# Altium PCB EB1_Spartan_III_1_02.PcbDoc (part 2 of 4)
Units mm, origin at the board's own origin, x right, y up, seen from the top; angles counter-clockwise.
Board outline 165.1 x 115.01 mm, 6 copper layers (Top Layer, MidLayer1, VCC Plane, GND Plane, MidLayer2, Bottom Layer); 356 components, 386 nets, 1788 pads, 779 vias.
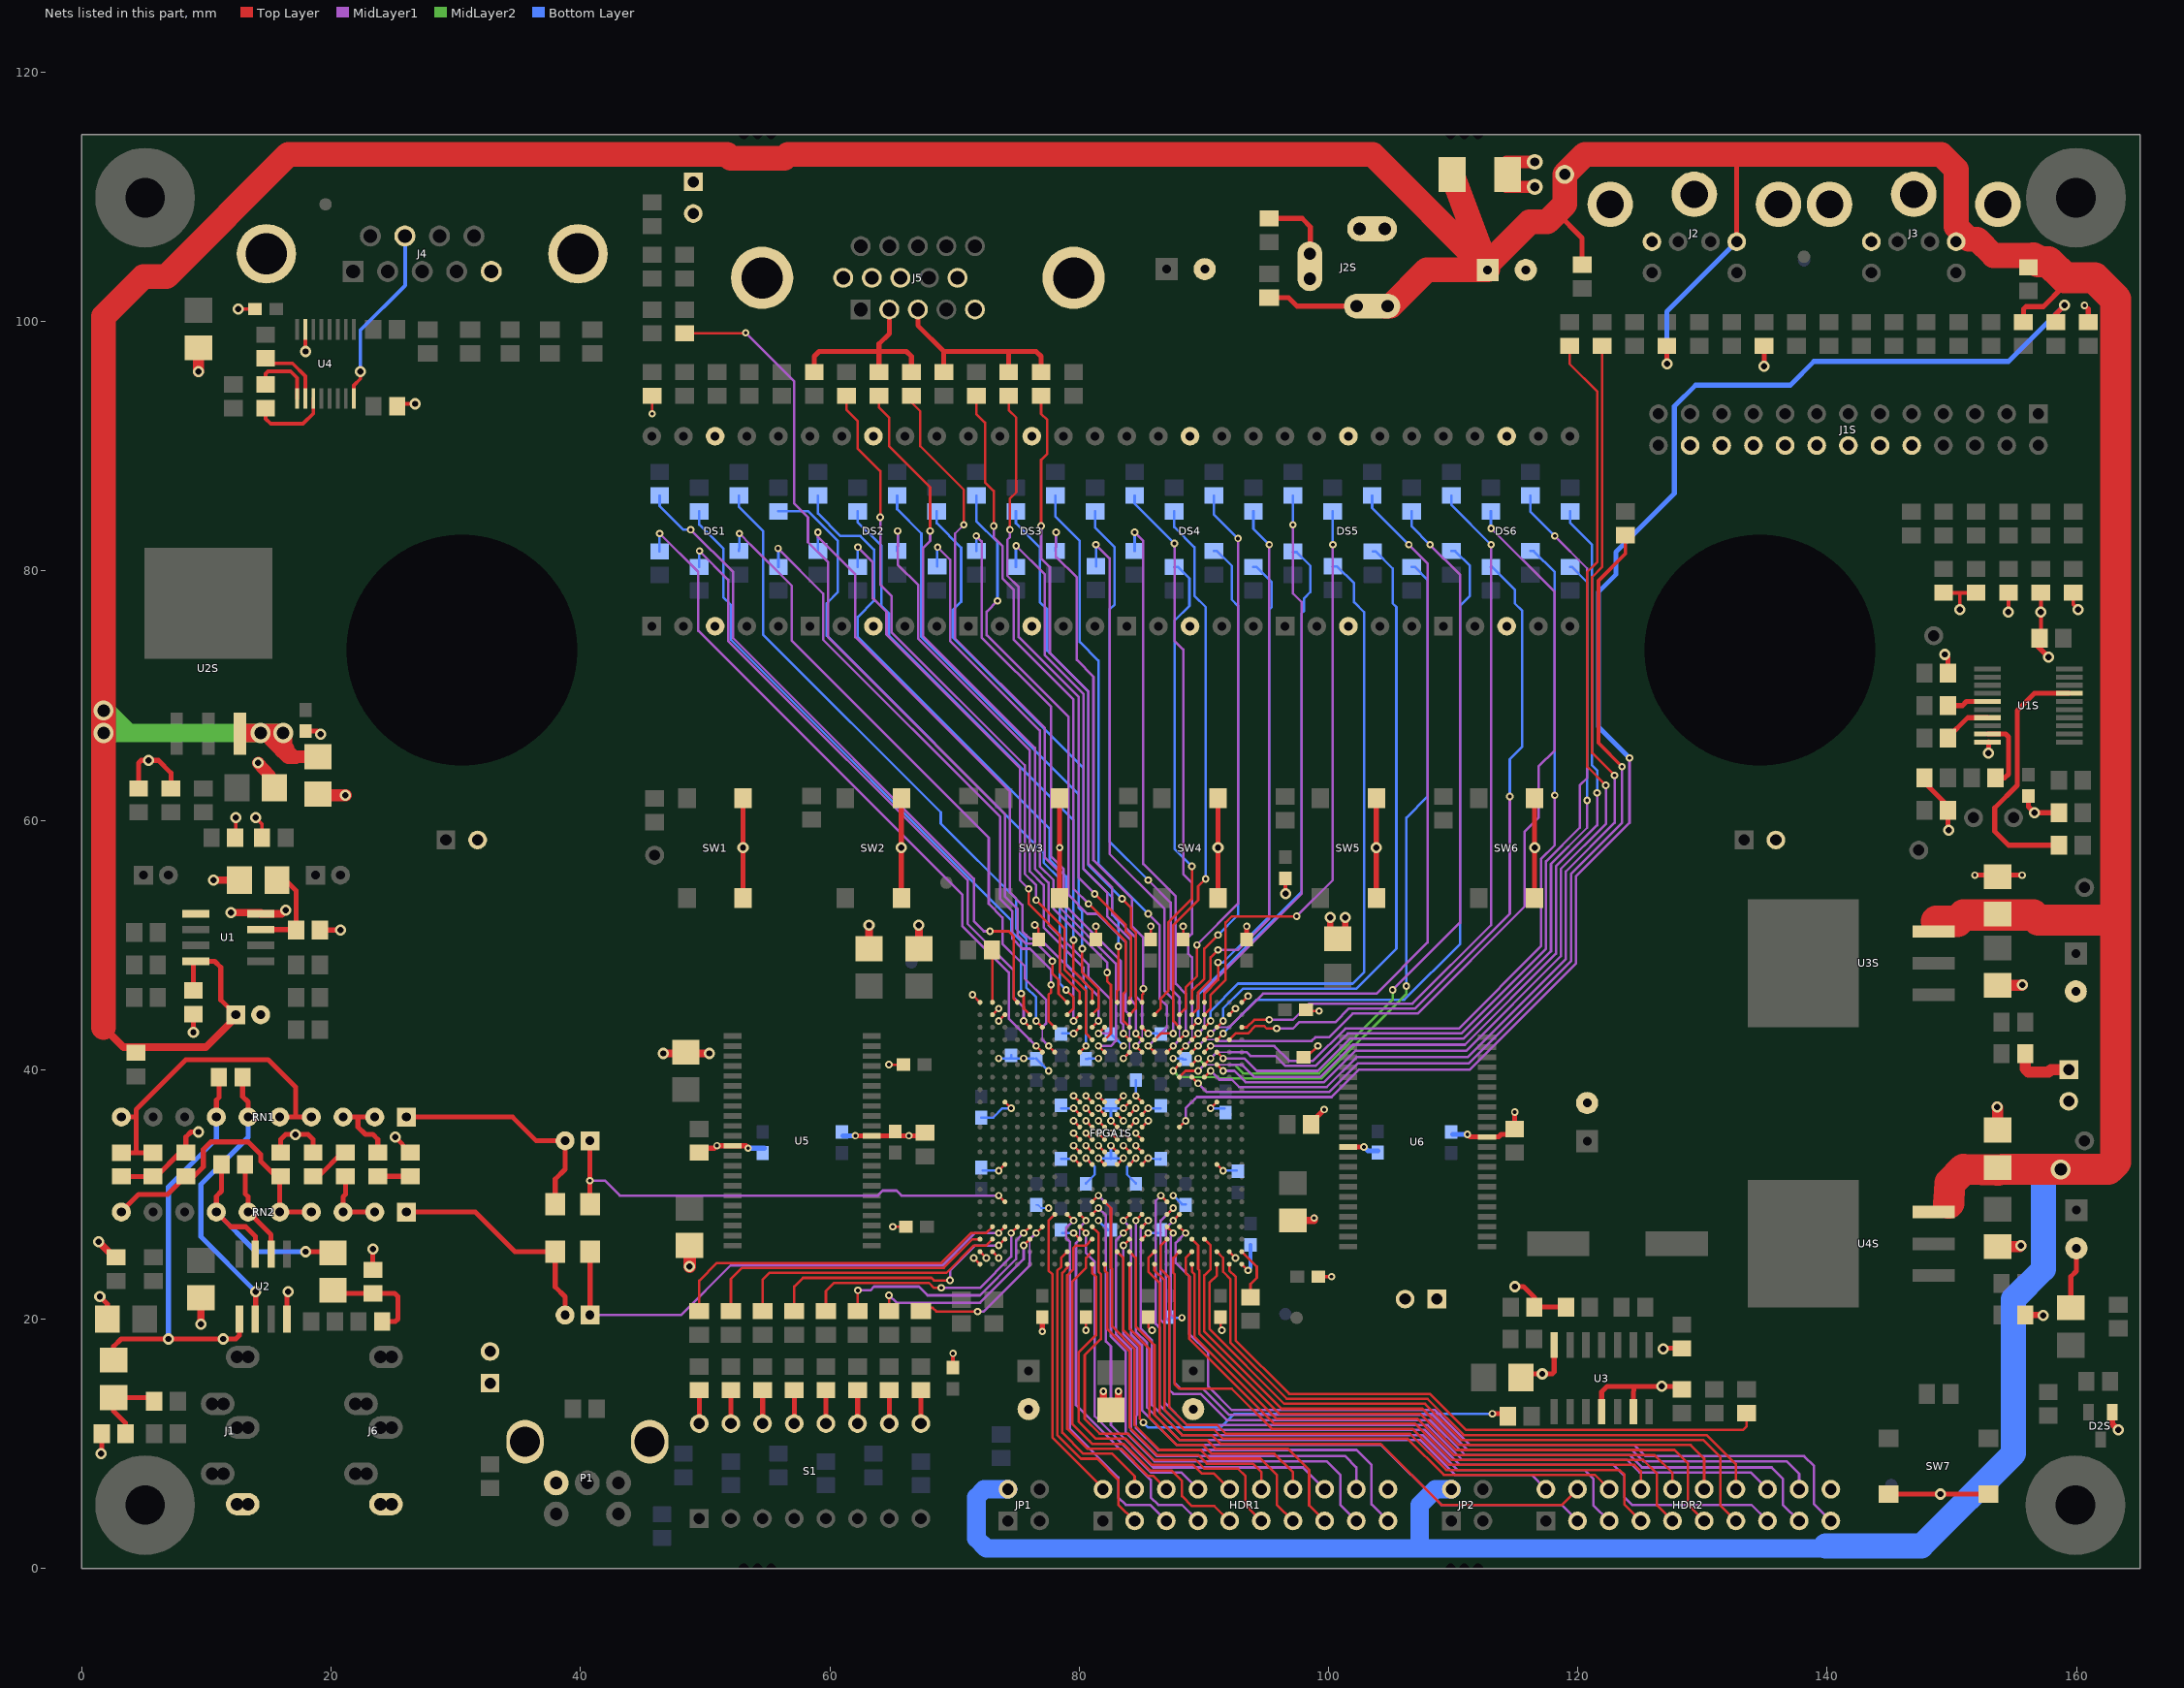
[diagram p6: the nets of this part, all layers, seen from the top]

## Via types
v1: diameter 0.6, hole 0.3, Top Layer to Bottom Layer, tented both sides, 427 vias
v2: diameter 1.6, hole 1, Top Layer to Bottom Layer, 224 vias
v3: diameter 0.9, hole 0.5, Top Layer to Bottom Layer, tented both sides, 126 vias
v4: diameter 1.27, hole 0.711, Top Layer to Bottom Layer, tented both sides, 2 vias

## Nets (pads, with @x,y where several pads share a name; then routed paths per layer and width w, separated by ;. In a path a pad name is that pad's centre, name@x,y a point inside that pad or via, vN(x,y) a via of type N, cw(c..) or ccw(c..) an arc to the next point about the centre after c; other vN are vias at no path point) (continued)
+5V: C37.1 C39.2 C70S.1 C73S.1 C75S.1 C77S.1 D1S.2 J2.5 J2S.1 J2S.1A J2S.1B J3.5 JP1.2 JP2.2 LED1.1 R6.2 R84.1 R85.1 R86.1 R87.1 TP6S.1 U1.8 U2S.3 U3S.3 U4S.3 | length 580.3
  Top Layer w0.4: C39.2@8.95,46.35 U1.8@8.95,48.6 ; U1.8@9.15,48.695 10.655,48.695 11.15,48.2 11.15,45.6 C37.1@12.35,44.4 ; LED1.1@95.25,101.92 96.8,101.92 97.485,101.235 J2S.1A@102.255,101.235 ; J2S.1@102.2,101.3 102.255,101.3 J2S.1@103.45,101.3 ; J2S.1@103.505,101.235 J2S.1@104.55,101.235 ; 118.25,108.8 118.3,108.75 120.35,106.7 R86.1@120.35,104.55 ; 122.55,113.4 122.555,113.595 125.65,113.4 ; v3(127.15,96.6) R87.1@127.15,98.05 ; 132.65,113.3 132.75,113.2 J2.5@132.75,106.4 ; R84.1@155.75,99.95 155.75,101 155.95,101.2 157.35,101.2 158.95,102.8
  Top Layer w0.6: 1.75,43.8 1.75,43.4 3.35,41.8 R6.2@4.35,41.8 ; R6.2@4.35,41.35 R6.2@4.35,41.8 ; C37.1@12.35,44.4 12.35,44.2 9.95,41.8 R6.2@4.35,41.8
  Top Layer w1: v2@14.75,66.8 15.35,66.2 16.55,65 17.15,65 ; v2@15.7,66.95 16.139,66.901 v2@16.15,66.9 ; 16.15,65.4 16.15,65.5 ; 16.15,65.7 16.15,65.5 ; v2(16.15,67) v2@16.15,66.9 ; 16.55,65.7 16.55,65.8 ; 16.95,65.2 16.15,66 v2@16.15,66.9 ; C73S.1@18.95,65.1 16.55,65.1 16.2,65.45 16.15,65.5
  Top Layer w1.5: U2S.3@12.95,67 v2(14.35,67) v2(16.15,67) 16.15,66.9 16.15,66 16.15,65.7
  Top Layer w2: 1.75,43.4 v2(1.75,67) v2(1.75,68.8) 1.75,100.4 4.95,103.6 6.784,103.6 16.55,113.4 51.75,113.4 52.05,113.1 56.35,113.1 56.65,113.4 103.55,113.4 C70S.1@112.776,104.14 ; J2S.1@104.55,101.235 J2S.1B@104.755,101.235 104.985,101.235 107.89,104.14 C70S.1@112.776,104.14 ; D1S.2@109.928,111.8 C70S.1@112.776,104.14 ; C70S.1@112.776,104.626 116.15,108 117.55,108 118.3,108.75 118.95,109.4 TP6S.1@118.95,111.8 120.55,113.4 122.55,113.4 125.65,113.4 149.15,113.4 150.35,112.2 150.35,107.6 150.95,107 151.35,106.6 152.05,106.6 153.35,105.3 156.15,105.3 156.65,105.3
  Top Layer w2.5: 148.75,51.9 150.45,51.9 150.95,52.4 153.67,52.4 156.55,52.4 156.95,52 163.15,52 ; 149.75,29.3 149.782,29.617 149.85,30.9 150.95,32 153.666,31.953 153.696,31.952 154.07,32 v2(158.75,32) 162.55,32 163.15,32.6 163.15,52 ; 156.551,105.096 156.775,104.975 156.95,104.8 157.75,104.8 159.05,103.5 161.45,103.5 163.15,101.8 163.15,52
  MidLayer2 w1.5: v2(16.15,67) v2(14.35,67) 3.75,67 ; 3.75,67 2.75,68 1.95,68.8 v2(1.75,68.8) v2(1.75,67) 3.75,67
  Bottom Layer w0.4: v3(127.15,96.6) 127.15,100.8 J2.5@132.75,106.4
  Bottom Layer w1.5: JP1.2@74.295,6.35 72.39,6.35 71.755,5.715 71.755,2.395 72.55,1.6 139.69,1.6 139.89,1.8 ; 107.315,1.905 107.315,5.08 108.585,6.35 JP2.2@109.855,6.35
  Bottom Layer w2: 139.89,1.8 147.55,1.8 154.95,9.2 154.95,21.6 157.35,24 157.35,32 ; 156.95,32 157.35,32 ; v2(158.75,32) 157.35,32
AUDIOL: C7.1 C41.1 FPGA1S.W3 | length 41.3
  Top Layer w0.2: v1(73.55,26.9) FPGA1S.W3@74.05,27.4
  Top Layer w0.4: C41.1@40.767,20.32 40.77,20.323 C7.1@40.77,25.4
  MidLayer1 w0.2: C41.1@40.767,20.32 48.07,20.32 52.05,24.3 69.05,24.3 71.65,26.9 v1(73.55,26.9)
AUDIOR: C6.1 C40.1 FPGA1S.U3 | length 39.4
  Top Layer w0.2: v1(73.55,29.9) FPGA1S.U3@74.05,29.4
  Top Layer w0.4: C40.1@40.767,34.29 40.767,31.1 40.767,29.213 C6.1@40.77,29.21
  MidLayer1 w0.2: v1(40.75,31.1) 41.95,31.1 43.15,29.9 63.85,29.9 64.25,30.3 65.35,30.3 65.75,29.9 v1(73.55,29.9)
BLUE0: FPGA1S.C13 R106.1 | length 55.9
  Top Layer w0.2: R106.1@71.75,94.05 71.75,92.6 72.45,91.9 72.45,87.1 73.15,86.4 v1(73.15,83.6) ; v1(80.75,53.3) 83.75,50.3 83.75,46.3 83.55,46.1 83.55,43.9 FPGA1S.C13@84.05,43.4
  MidLayer1 w0.2: v1(73.15,83.6) 73.15,82.7 73.85,82 73.85,79.4 74.75,78.5 74.75,74.5 79.55,69.7 79.55,54.5 v1(80.75,53.3)
BLUE1: FPGA1S.A13 R108.1 | length 53.3
  Top Layer w0.2: R108.1@74.35,94.05 74.35,92.9 74.95,92.3 74.95,86.3 74.45,85.8 v1(74.45,83.3) ; v1(81.25,54.1) 83.75,51.6 83.75,51.1 84.15,50.7 84.15,45.9 84.05,45.8 FPGA1S.A13@84.05,45.4
  MidLayer1 w0.2: v1(74.45,83.3) 74.45,82.7 74.25,82.5 74.25,79.6 75.15,78.7 75.15,74.7 79.95,69.9 79.95,55.4 v1(81.25,54.1)
BLUE2: FPGA1S.E14 R111.1 | length 56.8
  Top Layer w0.2: v1(76.95,83.6) 76.95,88.9 77.45,89.4 77.45,92.1 76.95,92.6 R111.1@76.95,94.05 ; v1(84.55,41.9) FPGA1S.E14@85.05,41.4
  MidLayer1 w0.127: 85.05,42.4 85.05,43.4
  MidLayer1 w0.2: v1(76.95,83.6) 76.95,81 77.65,80.3 77.65,73.4 80.75,70.3 80.75,56.5 82.65,54.6 82.65,52.5 84.55,50.6 84.55,45.9 85.05,45.4 85.05,43.4 ; v1(84.55,41.9) 85.05,42.4
BLUE#: J5.3 R107.2 R108.2 R111.2 | length 16.7
  Top Layer w0.4: J5.3@67.064,100.965 67.064,99.686 69.15,97.6 ; R107.2@69.15,95.95 69.15,97.6 ; R108.2@74.35,95.95 74.35,97.6 ; R111.2@76.95,96 76.95,97.2 76.55,97.6 74.35,97.6 ; 69.15,97.6 74.35,97.6
CTS: J4.7 U4.8 | length 14.8
  Top Layer w0.3: U4.8@21.825,93.825 21.825,94.875 22.35,95.4 v3(22.35,96)
  Bottom Layer w0.3: v3(22.35,96) 22.35,99.3 25.95,102.9 25.95,106.825 J4.7@25.92,106.855
DIG0_SEG0: FPGA1S.C6 R25.2 | length 52.7
  Top Layer w0.2: v1(76.55,43.9) FPGA1S.C6@77.05,43.4
  Bottom Layer w0.2: R25.2@52.705,86.045 52.705,85.145 54.65,83.2 54.65,74.9 68.906,60.644 68.906,59.744 74.95,53.7 74.95,51.3 75.75,50.5 75.75,46.6 76.55,45.8 v1(76.55,43.9)
DIG0_SEG1: FPGA1S.B8 R29.2 | length 52.5
  Top Layer w0.2: v1(78.95,46.4) 79.55,45.8 79.55,44.9 FPGA1S.B8@79.05,44.4
  Bottom Layer w0.2: R29.2@55.88,84.775 58.275,84.775 60.65,82.4 60.65,78.3 59.75,77.4 59.75,74.8 77.15,57.4 77.15,56.6 78.45,55.3 78.45,46.9 v1(78.95,46.4)
DIG0_SEG2: FPGA1S.E7 R33.2 | length 53.8
  Top Layer w0.2: v1(77.55,41.9) FPGA1S.E7@78.05,41.4
  MidLayer1 w0.127: 77.05,42.4 77.05,43.4
  MidLayer1 w0.2: v1(52.75,83) 53.643,82.093 ; 53.65,82.1 56.95,78.8 56.95,74.4 72.75,58.6 72.75,53.3 73.85,52.2 73.85,50.1 75.65,48.3 75.65,47.3 77.35,45.6 77.35,43.7 77.05,43.4 ; 77.05,42.4 v1(77.55,41.9)
  Bottom Layer w0.2: R33.2@52.705,81.595 52.705,81.755 52.75,81.8 v1(52.75,83)
DIG0_SEG3: FPGA1S.C5 R37.2 | length 50.5
  Top Layer w0.2: v1(75.55,43.9) FPGA1S.C5@76.05,43.4
  MidLayer1 w0.2: v1(49.55,81.6) 51.85,79.3 51.85,74.4 71.05,55.2 71.05,51.7 74.75,48 74.75,45.8 75.55,45 v1(75.55,43.9)
  Bottom Layer w0.2: R37.2@49.53,80.325 49.53,81.58 v1(49.55,81.6)
DIG0_SEG4: FPGA1S.E6 R41.2 | length 55.7
  Top Layer w0.2: v1(76.55,41.9) FPGA1S.E6@77.05,41.4
  MidLayer1 w0.2: v1(46.35,83) 49.45,79.9 49.45,75.2 70.65,54 70.65,51.5 74.35,47.8 74.35,44.1 v1(76.55,41.9)
  Bottom Layer w0.2: R41.2@46.35,81.57 v1(46.35,83)
DIG0_SEG5: FPGA1S.B5 R45.2 | length 51.4
  Top Layer w0.2: v1(75.35,46.1) 75.55,45.9 75.55,44.9 FPGA1S.B5@76.05,44.4
  Bottom Layer w0.2: R45.2@49.53,84.775 49.53,83.72 51.45,81.8 51.45,77.9 52.05,77.3 52.05,74.5 74.55,52 74.55,51.1 75.35,50.3 v1(75.35,46.1)
DIG0_SEG6: FPGA1S.A4 R49.2 | length 54.1
  Top Layer w0.2: v1(72.85,51.1) 74.35,51.1 74.75,50.7 74.75,45.7 FPGA1S.A4@75.05,45.4
  MidLayer1 w0.2: v1(48.85,83.3) 52.25,79.9 52.25,74.6 71.55,55.3 71.55,51.9 72.35,51.1 v1(72.85,51.1)
  Bottom Layer w0.2: R49.2@46.355,86.045 46.355,85.195 48.25,83.3 v1(48.85,83.3)
DIG0_SEG7: FPGA1S.C7 R53.2 | length 49.6
  Top Layer w0.2: v1(77.75,46.8) 77.75,46.2 77.55,46 77.55,43.9 FPGA1S.C7@78.05,43.4
  MidLayer1 w0.2: v1(55.85,81.8) 59.475,78.175 59.475,74.475 73.65,60.3 73.65,53.7 74.65,52.7 74.65,50.5 75.45,49.7 76.05,49.7 77.75,48 v1(77.75,46.8)
  Bottom Layer w0.2: v1(55.85,81.8) 55.88,81.77 R53.2@55.88,80.325
DIG1_SEG0: FPGA1S.B10 R26.2 | length 48.5
  Top Layer w0.2: v1(80.25,49.7) 80.25,47.8 81.55,46.5 81.55,44.9 FPGA1S.B10@81.05,44.4
  Bottom Layer w0.2: R26.2@65.405,86.045 65.405,84.945 67.35,83 67.35,74.7 79.95,62.1 79.95,53 80.25,52.7 v1(80.25,49.7)
DIG1_SEG1: FPGA1S.A12 R30.2 | length 46
  Top Layer w0.2: FPGA1S.A12@83.05,45.4 83.05,46.3 83.15,46.4 v1(83.15,49.9)
  Bottom Layer w0.2: R30.2@68.58,84.775 68.58,83.82 70.536,81.864 70.536,77.521 69.85,76.835 69.85,74.7 80.35,64.2 80.35,56.1 82.65,53.8 82.65,52.4 83.15,51.9 v1(83.15,49.9)
DIG1_SEG2: FPGA1S.C10 R34.2 | length 48.3
  Top Layer w0.2: FPGA1S.C10@81.05,43.4 v1(81.55,43.9)
  MidLayer1 w0.2: v1(65.45,83.2) 65.45,80.5 67.101,78.849 67.101,74.549 76.05,65.6 76.05,55.9 77.15,54.8 77.15,51.4 80.35,48.2 80.35,47.1 81.55,45.9 v1(81.55,43.9)
  Bottom Layer w0.2: R34.2@65.405,81.595 65.405,81.955 65.45,82 v1(65.45,83.2)
DIG1_SEG3: FPGA1S.A9 R38.2 | length 45.5
  Top Layer w0.2: v1(75.95,54.5) 75.95,53.3 78.45,50.8 78.45,47.8 80.05,46.2 FPGA1S.A9@80.05,45.4
  MidLayer1 w0.2: v1(62.25,81.9) 63.45,80.7 63.45,77.8 64.55,76.7 64.55,74.9 75.25,64.2 75.25,55.2 v1(75.95,54.5)
  Bottom Layer w0.2: R38.2@62.23,80.325 62.23,80.48 62.25,80.5 v1(62.25,81.9)
DIG1_SEG4: FPGA1S.B9 R42.2 | length 50.4
  Top Layer w0.2: v1(79.55,43.9) FPGA1S.B9@80.05,44.4
  MidLayer1 w0.2: v1(59.05,83.1) 59.05,82.7 62.05,79.7 62.05,74.7 74.45,62.3 74.45,54.2 75.45,53.2 75.45,51.1 75.761,50.789 76.05,50.5 76.85,50.5 79.55,47.8 v1(79.55,43.9)
  Bottom Layer w0.2: v1(59.05,83.1) 59.055,83.095 R42.2@59.055,81.595
DIG1_SEG5: FPGA1S.A10 R46.2 | length 47.2
  Top Layer w0.2: v1(79.55,50.4) 79.55,47.9 81.05,46.4 FPGA1S.A10@81.05,45.4
  Bottom Layer w0.2: R46.2@62.23,84.775 62.23,83.92 64.15,82 64.15,77.2 64.75,76.6 64.75,74.8 79.55,60 v1(79.55,50.4)
DIG1_SEG6: FPGA1S.E9 R50.2 | length 55.8
  Top Layer w0.2: FPGA1S.E9@80.05,41.4 v1(80.55,41.9)
  Bottom Layer w0.2: R50.2@59.055,86.045 59.055,84.595 60.85,82.8 62.45,82.8 63.55,81.7 63.55,77.6 62.25,76.3 62.25,74.7 77.65,59.3 77.65,56.8 78.95,55.5 78.95,48.5 80.55,46.9 v1(80.55,41.9)
DIG1_SEG7: FPGA1S.D11 R54.2 | length 47
  Top Layer w0.2: FPGA1S.D11@82.05,42.4 82.55,42.9 82.55,46.8 82.25,47.1 v1(82.25,47.8)
  MidLayer1 w0.2: v1(68.65,81.9) 69.65,80.9 69.65,74.4 76.85,67.2 76.85,56.3 77.95,55.2 77.95,52.9 82.25,48.6 v1(82.25,47.8)
  Bottom Layer w0.2: R54.2@68.623,80.347 68.623,81.873 v1(68.65,81.9)
DIG2_SEG0: FPGA1S.E15 R27.2 | length 49.2
  Top Layer w0.2: v1(85.55,41.9) FPGA1S.E15@86.05,41.4
  MidLayer1 w0.127: 87.05,43.4 87.05,44.4
  MidLayer1 w0.2: v1(85.55,41.9) 87.05,43.4 ; v1(85.55,52.5) 86.45,51.6 86.45,45.7 87.05,45.1 87.05,44.4
  Bottom Layer w0.2: R27.2@78.105,86.045 78.105,84.345 80.05,82.4 80.05,74.3 81.55,72.8 81.55,56.5 v1(85.55,52.5)
DIG2_SEG1: FPGA1S.E16 R31.2 | length 46.9
  Top Layer w0.2: FPGA1S.E16@87.05,41.4 v1(87.55,41.9)
  MidLayer1 w0.127: 88.05,42.4 88.05,43.4
  MidLayer1 w0.2: v1(85.55,55.2) 87.35,53.4 87.35,46.5 88.05,45.8 88.05,43.4 ; v1(87.55,41.9) 88.05,42.4
  Bottom Layer w0.2: R31.2@81.28,84.775 81.28,83.47 82.85,81.9 82.85,77.3 82.45,76.9 82.45,58.3 v1(85.55,55.2)
DIG2_SEG2: FPGA1S.A14 R35.2 | length 42.2
  Top Layer w0.2: FPGA1S.A14@85.05,45.4 85.05,46 85.15,46.1 v1(85.15,46.5)
  MidLayer1 w0.2: v1(78.15,83.1) 78.15,81.1 79.814,79.466 79.814,72.866 81.15,71.5 81.15,56.8 84.25,53.7 84.25,51.5 85.15,50.6 v1(85.15,46.5)
  Bottom Layer w0.2: R35.2@78.105,81.595 78.105,81.855 78.15,81.9 v1(78.15,83.1)
DIG2_SEG3: FPGA1S.D14 R39.2 | length 45.5
  Top Layer w0.2: v1(84.55,42.9) FPGA1S.D14@85.05,42.4
  MidLayer1 w0.2: v1(74.95,82) 77.25,79.7 77.25,73.234 80.35,70.134 80.35,56.1 82.25,54.2 82.25,52.3 84.15,50.4 84.15,45.6 84.55,45.2 v1(84.55,42.9)
  Bottom Layer w0.2: R39.2@74.93,80.325 74.93,81.98 v1(74.95,82)
DIG2_SEG4: FPGA1S.D13 R43.2 | length 46.7
  Top Layer w0.2: v1(83.55,42.9) FPGA1S.D13@84.05,42.4
  MidLayer1 w0.2: v1(71.75,82.8) 72.187,82.363 72.187,74.651 77.75,69.1 77.75,57.1 78.75,56.1 78.75,53.3 83.35,48.7 83.35,43.8 83.55,43.6 v1(83.55,42.9)
  Bottom Layer w0.2: v1(71.75,82.8) 71.755,82.795 R43.2@71.755,81.595
DIG2_SEG5: FPGA1S.B13 R47.2 | length 44.6
  Top Layer w0.2: v1(83.45,53.7) 84.15,53 84.15,51.4 84.55,51 84.55,44.9 FPGA1S.B13@84.05,44.4
  Bottom Layer w0.2: R47.2@74.93,84.775 74.93,83.82 76.85,81.9 76.85,77.5 77.45,76.9 77.45,73.6 80.75,70.3 80.75,56.4 v1(83.45,53.7)
DIG2_SEG6: FPGA1S.E13 R51.2 | length 52.3
  Top Layer w0.2: v1(83.55,40.9) FPGA1S.E13@84.05,41.4
  MidLayer1 w0.127: 84.05,41.4 84.05,43.4
  MidLayer1 w0.2: v1(73.45,77.6) 72.593,76.733 72.593,74.854 79.15,68.3 79.15,54 80.65,52.5 81.45,52.5 83.75,50.2 83.75,44.7 84.05,44.4 84.05,43.4 ; v1(83.55,40.9) 84.05,41.4
  Bottom Layer w0.2: R51.2@71.755,86.045 71.755,83.995 73.45,82.3 v1(73.45,77.6)
DIG2_SEG7: FPGA1S.D15 R55.2 | length 45.2
  Top Layer w0.2: FPGA1S.D15@86.05,42.4 86.55,42.9 v1(87.55,42.9)
  MidLayer1 w0.2: v1(81.35,82.1) 82.45,81 82.45,57.3 86.85,52.9 86.85,46.3 87.55,45.6 v1(87.55,42.9)
  Bottom Layer w0.2: R55.2@81.35,80.37 v1(81.35,82.1)
DIG3_SEG0: FPGA1S.B17 R28.2 | length 44.4
  Top Layer w0.2: FPGA1S.B17@88.05,44.4 88.55,44.9 88.55,46.6 89.45,47.5 v1(89.45,50)
  MidLayer1 w0.2: v1(89.45,50) 92.75,53.3 v1(92.75,82.6)
  Bottom Layer w0.2: R28.2@90.805,86.045 90.805,84.545 v1(92.75,82.6)
DIG3_SEG1: FPGA1S.B18 R32.2 | length 44.4
  Top Layer w0.2: FPGA1S.B18@89.05,44.4 89.55,44.9 89.55,46.2 90.55,47.2 90.55,49 v1(91.15,49.6)
  MidLayer1 w0.2: v1(91.15,49.6) 92.75,49.6 95.25,52.1 v1(95.25,82.1)
  Bottom Layer w0.2: R32.2@93.98,84.775 93.98,83.37 v1(95.25,82.1)
DIG3_SEG2: FPGA1S.A18 R36.2 | length 38.7
  Top Layer w0.2: FPGA1S.A18@89.05,45.4 89.05,46.3 90.05,47.3 90.05,49.7 v1(91.15,50.8)
  Bottom Layer w0.2: R36.2@90.805,81.595 91.055,81.595 92.25,80.4 92.25,77.7 92.75,77.2 92.75,52.4 v1(91.15,50.8)
DIG3_SEG3: FPGA1S.B15 R40.2 | length 38.9
  Top Layer w0.2: FPGA1S.B15@86.05,44.4 86.55,44.9 86.55,45.7 87.15,46.3 87.15,51.8 89.05,53.7 v1(89.05,56.3)
  Bottom Layer w0.2: R40.2@87.63,80.325 87.925,80.325 88.85,79.4 88.85,77.2 87.65,76 87.65,57.7 v1(89.05,56.3)
DIG3_SEG4: FPGA1S.D17 R44.2 | length 44.1
  Top Layer w0.2: FPGA1S.D17@88.05,42.4 v1(88.55,42.9)
  MidLayer1 w0.2: v1(84.45,83.1) 85.15,82.4 85.15,56.5 87.75,53.9 87.75,46.9 88.55,46.1 v1(88.55,42.9)
  Bottom Layer w0.2: v1(84.45,83.1) 84.455,83.095 R44.2@84.455,81.595
DIG3_SEG5: FPGA1S.C17 R48.2 | length 43.7
  Top Layer w0.2: FPGA1S.C17@88.05,43.4 87.55,43.9 87.55,51.6 89.55,53.6 89.55,54.7 v1(90.15,55.3)
  Bottom Layer w0.2: R48.2@87.63,84.775 87.63,83.52 89.25,81.9 89.25,78 90.15,77.1 v1(90.15,55.3)
DIG3_SEG6: FPGA1S.E17 R52.2 | length 47.2
  Top Layer w0.2: FPGA1S.E17@88.05,41.4 v1(88.55,41.9)
  MidLayer1 w0.127: 89.05,42.4 89.05,44.4
  MidLayer1 w0.2: v1(87.65,82.2) 87.65,74.4 88.35,73.7 88.35,55.7 89.05,55 89.05,50.9 88.75,50.6 88.75,49.3 89.05,49 89.05,44.4 ; v1(88.55,41.9) 89.05,42.4
  Bottom Layer w0.2: R52.2@84.455,86.045 84.455,85.395 v1(87.65,82.2)
DIG3_SEG7: FPGA1S.A19 R56.2 | length 38.1
  Top Layer w0.2: FPGA1S.A19@90.05,45.4 90.05,46.1 91.15,47.2 v1(91.15,48.6)
  Bottom Layer w0.2: v1(91.15,48.6) 91.55,48.6 95.25,52.3 95.25,76.9 95.45,77.1 95.45,79.1 94.225,80.325 R56.2@93.98,80.325
DIG4_SEG0: FPGA1S.D19 R57.2 | length 58.8
  Top Layer w0.2: FPGA1S.D19@90.05,42.4 v1(90.55,42.9)
  MidLayer1 w0.127: 91.05,43.4 92.05,43.4
  MidLayer1 w0.2: v1(90.55,42.9) 91.05,43.4 ; 92.05,43.4 94.75,46.1 103.85,46.1 107.95,50.2 107.95,80.6 v1(106.45,82.1)
  Bottom Layer w0.2: R57.2@103.505,86.045 103.505,85.045 v1(106.45,82.1)
DIG4_SEG1: FPGA1S.F18 R59.2 | length 62.3
  Top Layer w0.2: FPGA1S.F18@89.05,40.4 v1(89.55,40.9)
  MidLayer1 w0.2: v1(105.15,46.4) 110.55,51.8 110.55,79.7 v1(108.15,82.1)
  MidLayer2 w0.127: 90.023,40.427 90.05,40.4 92.05,40.4
  MidLayer2 w0.2: v1(89.55,40.9) 90.05,40.4 ; 92.05,40.4 92.45,40.4 93.15,39.7 99.25,39.7 105.15,45.6 v1(105.15,46.4)
  Bottom Layer w0.2: R59.2@106.68,84.775 106.68,83.57 v1(108.15,82.1)
DIG4_SEG2: FPGA1S.C20 R61.2 | length 50.4
  Top Layer w0.2: FPGA1S.C20@91.05,43.4 v1(91.55,43.9)
  Bottom Layer w0.2: v1(91.55,43.9) 91.55,44.9 93.15,46.5 102.25,46.5 105.45,49.7 105.45,77.1 105.15,77.4 105.15,80.2 103.78,81.57 R61.2@103.55,81.57
DIG4_SEG3: FPGA1S.C19 R63.2 | length 48.9
  Top Layer w0.2: FPGA1S.C19@90.05,43.4 v1(90.55,43.9)
  Bottom Layer w0.2: v1(90.55,43.9) 90.55,44.7 92.75,46.9 101.95,46.9 102.85,47.8 102.85,76.7 102.05,77.5 102.05,79 100.68,80.37 R63.2@100.35,80.37
DIG4_SEG4: FPGA1S.C18 R65.2 | length 42.8
  Top Layer w0.2: FPGA1S.C18@89.05,43.4 v1(89.55,43.9)
  Bottom Layer w0.2: v1(89.55,43.9) 89.55,46 97.85,54.3 97.85,76.6 98.05,76.8 98.05,77.8 98.55,78.3 98.55,80.4 97.45,81.5 R65.2@97.15,81.5
DIG4_SEG5: FPGA1S.B19 R67.2 | length 47.7
  Top Layer w0.2: FPGA1S.B19@90.05,44.4 90.55,44.9 90.55,46 91.75,47.2 91.75,51.8 92.25,52.3 v1(97.45,52.3)
  MidLayer1 w0.2: v1(97.45,52.3) 100.35,55.2 v1(100.35,82.1)
  Bottom Layer w0.2: R67.2@100.33,84.775 100.33,84.22 100.35,84.2 v1(100.35,82.1)
DIG4_SEG6: FPGA1S.D18 R69.2 | length 47.6
  Top Layer w0.2: FPGA1S.D18@89.05,42.4 v1(89.55,42.9)
  MidLayer1 w0.127: 90.05,43.4 90.05,44.4
  MidLayer1 w0.2: v1(89.55,42.9) 90.05,43.4 ; 90.05,44.4 90.05,46.3 97.85,54.1 97.85,77.5 97.15,78.2 v1(97.15,83.7)
  Bottom Layer w0.2: v1(97.15,83.7) 97.15,85.6 97.155,85.605 R69.2@97.155,86.045
DIG4_SEG7: FPGA1S.F17 R71.2 | length 58.1
  Top Layer w0.2: v1(87.55,39.9) FPGA1S.F17@88.05,40.4
  MidLayer2 w0.127: 89.05,39.4 91.15,39.4
  MidLayer2 w0.2: v1(87.55,39.9) 88.05,39.4 89.05,39.4 ; 91.15,39.4 91.25,39.3 99.45,39.3 106.25,46.1 v1(106.25,46.7)
  Bottom Layer w0.2: v1(106.25,46.7) 106.25,60.2 107.95,61.9 107.95,79.3 106.925,80.325 R71.2@106.68,80.325
DIG5_SEG0: FPGA1S.F19 R58.2 | length 71.8
  Top Layer w0.2: FPGA1S.F19@90.05,40.4 v1(90.55,40.9)
  MidLayer1 w0.127: 91.05,41.4 92.05,41.4
  MidLayer1 w0.2: v1(90.55,40.9) 91.05,41.4 ; 92.05,41.4 93.45,41.4 93.75,41.1 95.75,41.1 96.55,40.3 98.95,40.3 101.55,42.9 110.65,42.9 117.45,49.7 117.45,56.7 120.15,59.4 120.15,62.8 120.75,63.4 120.75,80.2 v1(118.15,82.8)
  Bottom Layer w0.2: R58.2@116.205,86.045 116.205,84.745 v1(118.15,82.8)
DIG5_SEG1: FPGA1S.G17 R60.2 | length 72.9
  Top Layer w0.2: FPGA1S.G17@88.05,39.4 88.55,39.9 v1(89.55,39.9)
  MidLayer1 w0.127: 90.05,40.4 92.05,40.4
  MidLayer1 w0.2: v1(89.55,39.9) 90.05,40.4 ; 92.05,40.4 93.05,40.4 94.05,39.4 99.35,39.4 101.95,42 110.95,42 118.25,49.3 118.25,56.3 121.55,59.6 v1(121.55,62.2)
  Bottom Layer w0.2: R60.2@119.38,84.775 119.38,83.87 121.15,82.1 121.15,64.4 121.55,64 v1(121.55,62.2)
DIG5_SEG2: FPGA1S.E19 R62.2 | length 64.6
  Top Layer w0.2: FPGA1S.E19@90.05,41.4 v1(90.55,41.9)
  MidLayer1 w0.2: v1(90.55,41.9) 95.65,41.9 96.85,40.7 98.75,40.7 101.35,43.3 110.45,43.3 117.05,49.9 117.05,56.9 118.15,58 v1(118.15,62)
  Bottom Layer w0.2: R62.2@116.205,81.595 116.455,81.595 118.15,79.9 v1(118.15,62)
DIG5_SEG3: FPGA1S.D21 R64.2 | length 56.2
  Top Layer w0.2: FPGA1S.D21@92.05,42.4 92.55,42.9 93.55,42.9 94.15,43.5 94.85,43.5 95.05,43.3 v1(95.85,43.3)
  MidLayer1 w0.2: v1(95.85,43.3) 97.15,43.3 97.65,43.8 100.55,43.8 101.65,44.9 106.95,44.9 114.55,52.5 v1(114.55,61.9)
  Bottom Layer w0.2: R64.2@113.03,80.325 113.125,80.325 114.95,78.5 114.95,77.4 115.55,76.8 115.55,65.9 114.55,64.9 v1(114.55,61.9)
DIG5_SEG4: FPGA1S.D20 R66.2 | length 55.3
  Top Layer w0.2: FPGA1S.D20@91.05,42.4 v1(91.55,42.9)
  Bottom Layer w0.2: v1(91.55,42.9) 94.25,45.6 106.084,45.6 110.55,50.066 110.55,77.2 111.35,78 111.35,80.4 110.155,81.595 R66.2@109.855,81.595
DIG5_SEG5: FPGA1S.E18 R68.2 | length 66.4
  Top Layer w0.2: FPGA1S.E18@89.05,41.4 v1(89.55,41.9)
  MidLayer1 w0.127: 90.05,42.4 91.05,42.4
  MidLayer1 w0.2: v1(89.55,41.9) 90.05,42.4 ; 91.05,42.4 91.15,42.3 98.65,42.3 98.95,42.6 100.05,42.6 101.95,44.5 107.15,44.5 115.75,53.1 115.75,59.1 116.85,60.2 116.85,64.3 118.15,65.6 118.15,78.3 v1(113.05,83.4)
  Bottom Layer w0.2: R68.2@113.03,84.775 113.03,83.42 v1(113.05,83.4)
DIG5_SEG6: FPGA1S.C22 R70.2 | length 59.2
  Top Layer w0.2: FPGA1S.C22@93.05,43.4 93.45,43.4 94.05,44 v1(95.25,44)
  MidLayer1 w0.2: v1(95.25,44) 97.15,44 98.45,45.3 106.75,45.3 113.05,51.6 v1(113.05,82.1)
  Bottom Layer w0.2: R70.2@109.855,86.045 109.855,85.295 v1(113.05,82.1)
DIG5_SEG7: FPGA1S.E20 R72.2 | length 64.1
  Top Layer w0.2: FPGA1S.E20@91.05,41.4 v1(91.55,40.9)
  MidLayer1 w0.2: v1(91.55,40.9) 93.25,40.9 94.25,39.9 99.15,39.9 101.75,42.5 110.85,42.5 117.85,49.5 117.85,56.5 120.75,59.4 v1(120.75,61.6)
  Bottom Layer w0.2: R72.2@119.38,80.325 119.525,80.325 120.75,79.1 v1(120.75,61.6)
FCLK: FPGA1S.AA12 R122.1 | length 44.4
  Top Layer w0.2: FPGA1S.AA12@83.05,25.4 83.55,24.9 83.55,19.1 84.85,17.8 84.85,12.034 85.15,11.734 v1(85.15,11.7)
  Top Layer w0.4: v1(113.15,12.4) R122.1@114.4,12.4
  Bottom Layer w0.2: v1(85.15,11.7) 85.55,11.3 91.35,11.3 92.45,12.4 v1(113.15,12.4)
FPGA_CCLK: FPGA1S.AA22 R1S.2 | length 4.4
  Top Layer w0.2: FPGA1S.AA22@93.05,25.4 94.25,24.2 94.25,23.3 93.75,22.8 R1S.2@93.75,21.75
FPGA_PROGRAM: FPGA1S.A2 R2S.2 | length 4
  Top Layer w0.2: FPGA1S.A2@73.05,45.4 R2S.2@73.05,49.4
GND: C1S.2 C2S.2 C3.2 C3S.2 C4.2 C4S.2 C5.2 C5S.2 C6S.2 C7S.2 C8S.2 C9.1 C9S.2 C10S.2 C11.1 C11S.2 C12S.2 C13S.2 C14.1 C14S.2 C15.1 C15S.2 C16.1 C16S.2 C17.1 C17S.2 C18.2 C18S.2 C19.2 C19S.2 C20S.2 C21S.2 C22S.2 C23.2 C23S.2 C24.2 C24S.2 C25.1 C25S.2 C26.1 C26S.2 C27.1 C27S.2 C28.1 C28S.2 C29.1 C29S.2 C30.1 C30S.2 C31.2 C31S.2 C32.1 C32S.2 C33S.2 C34.1 C34S.2 C35S.2 C36S.2 C37.2 C37S.2 C38S.2 C39.1 C39S.2 C40S.2 C41S.2 C42S.2 C43S.2 C44S.2 C45S.2 C46S.2 C47S.2 C48S.2 C49S.2 C50S.2 C51S.2 C52S.2 C53S.2 C54S.2 C55S.2 C56S.2 C57S.2 C58S.2 C59S.2 C60S.2 C61S.2 C62S.2 C63S.2 C64S.2 C65S.2 C66S.2 C67S.2 C68S.2 C69S.2 C70S.2 C71S.2 C72S.2 C73S.2 C74S.2 C75S.2 C76S.2 C77S.2 C78S.2 C79S.1 C80S.2 D1S.1 D2S.1 DS1.3 DS1.8 DS2.3 DS2.8 DS3.3 DS3.8 DS4.3 DS4.8 DS5.3 DS5.8 DS6.3 DS6.8 FPGA1S.A1 FPGA1S.A22 FPGA1S.AA1 FPGA1S.AA2 FPGA1S.AA21 FPGA1S.AB1 FPGA1S.AB22 FPGA1S.B2 FPGA1S.B3 FPGA1S.B21 FPGA1S.C9 FPGA1S.C14 FPGA1S.J3 FPGA1S.J9 FPGA1S.J10 FPGA1S.J11 FPGA1S.J12 FPGA1S.J13 FPGA1S.J14 FPGA1S.J20 FPGA1S.K9 FPGA1S.K10 FPGA1S.K11 FPGA1S.K12 FPGA1S.K13 FPGA1S.K14 FPGA1S.L9 FPGA1S.L10 FPGA1S.L11 FPGA1S.L12 FPGA1S.L13 FPGA1S.L14 FPGA1S.M9 FPGA1S.M10 FPGA1S.M11 FPGA1S.M12 FPGA1S.M13 FPGA1S.M14 FPGA1S.N9 FPGA1S.N10 FPGA1S.N11 FPGA1S.N12 FPGA1S.N13 FPGA1S.N14 FPGA1S.P3 FPGA1S.P9 FPGA1S.P10 FPGA1S.P11 FPGA1S.P12 FPGA1S.P13 FPGA1S.P14 FPGA1S.P20 FPGA1S.Y9 FPGA1S.Y14 GJ1S.1 GJ1S.2 GJ2S.1 GJ2S.2 GJ3S.1 GJ3S.2 GJ4S.1 GJ4S.2 HDR1.20 HDR2.20 J1.1 J1.1A J1.1B J1S.18 J1S.19 J1S.20 J1S.21 J1S.22 J1S.23 J1S.24 J1S.25 J2.3 J2.MH1 J2.MH2 J2.MH3 J2S.2 J2S.2A J2S.2B J2S.3 J2S.3A J2S.3B J3.3 J3.MH1 J3.MH2 J3.MH3 J4.5 J4.10 J4.11 J5.5 J5.6 J5.7 J5.8 J5.10 J5.16 J5.17 J6.1 J6.1A J6.1B LS1.2 LS2.2 P1.3 P1.6 P1.7 R4.2 R5.2 R5S.1 R6S.1 R7S.1 R8.2 R8S.1 R31S.1 R34S.1 R35S.1 R36S.1 R74.1 R75.1 R76.1 R77.1 R78.1 R79.1 R80.1 R81.1 R83.1 R120.1 R121.1 S1.9 S1.10 S1.11 S1.12 S1.13 S1.14 S1.15 S1.16 SW1.3 SW1.4 SW2.3 SW2.4 SW3.3 SW3.4 SW4.3 SW4.4 SW5.3 SW5.4 SW6.3 SW6.4 SW7.3 SW7.4 U1.4 U1.5 U1S.10 U2.4 U3.7 U3.11 U3.13 U4.15 U5.12 U5.34 U6.12 U6.34 | length 356.8
  Top Layer w0.2: v1(45.75,92.6) C24.2@45.75,94.05 ; v1(64.75,40.4) C10S.2@65.9,40.4 ; v1@64.85,27.4 v1(65.05,27.4) C35S.2@65.9,27.4 ; v1(71.45,46) FPGA1S.A1@72.05,45.4 ; v1(71.55,24.9) FPGA1S.AB1@72.05,24.4 ; FPGA1S.AA1@72.05,25.4 v1(72.55,24.9) ; FPGA1S.AA2@73.05,25.4 v1(73.55,24.9) ; FPGA1S.B2@73.05,44.4 v1(73.55,44.9) ; v1(73.55,31.9) FPGA1S.P3@74.05,32.4 ; v1(73.55,43.9) FPGA1S.B3@74.05,44.4 ; FPGA1S.J3@74.05,37.4 v1(74.55,36.9) ; v1(76.45,51.6) 76.75,51.3 C40S.2@76.75,50.45 ; v1(79.55,26.9) FPGA1S.Y9@80.05,26.4 ; v1(79.55,32.9) FPGA1S.P9@80.05,32.4 ; v1(79.55,33.9) FPGA1S.N9@80.05,33.4 ; v1(79.55,34.9) FPGA1S.M9@80.05,34.4 ; v1(79.55,35.9) FPGA1S.L9@80.05,35.4 ; v1(79.55,36.9) FPGA1S.K9@80.05,36.4 ; v1(79.55,37.9) FPGA1S.J9@80.05,37.4 ; v1(79.55,42.9) FPGA1S.C9@80.05,43.4 ; v1(80.55,19.1) C7S.2@80.55,20.15 ; v1(80.55,32.9) FPGA1S.P10@81.05,32.4 ; v1(80.55,33.9) FPGA1S.N10@81.05,33.4 ; v1(80.55,34.9) FPGA1S.M10@81.05,34.4 ; v1(80.55,35.9) FPGA1S.L10@81.05,35.4 ; v1(80.55,36.9) FPGA1S.K10@81.05,36.4 ; v1(80.55,37.9) FPGA1S.J10@81.05,37.4 ; C16S.2@81.35,50.45 v1(81.35,51.5) ; v1(81.55,32.9) FPGA1S.P11@82.05,32.4 ; v1(81.55,33.9) FPGA1S.N11@82.05,33.4 ; v1(81.55,34.9) FPGA1S.M11@82.05,34.4 ; v1(81.55,35.9) FPGA1S.L11@82.05,35.4 ; v1(81.55,36.9) FPGA1S.K11@82.05,36.4 ; v1(81.55,37.9) FPGA1S.J11@82.05,37.4 ; v1(82.55,33.9) FPGA1S.N12@83.05,33.4 ; v1(82.55,34.9) FPGA1S.M12@83.05,34.4 ; v1(82.55,35.9) FPGA1S.L12@83.05,35.4 ; FPGA1S.P12@83.05,32.4 v1(83.55,32.9) ; FPGA1S.K12@83.05,36.4 v1(83.55,35.9) ; FPGA1S.J12@83.05,37.4 v1(83.55,37.9) ; v1(83.55,33.9) FPGA1S.N13@84.05,33.4 ; v1(83.55,34.9) FPGA1S.M13@84.05,34.4 ; v1(83.55,36.9) FPGA1S.J13@84.05,37.4 ; FPGA1S.P13@84.05,32.4 v1(84.55,32.9) ; FPGA1S.L13@84.05,35.4 v1(84.55,35.9) ; FPGA1S.K13@84.05,36.4 v1(84.55,36.9) ; v1(84.55,33.9) FPGA1S.N14@85.05,33.4 ; v1(84.55,34.9) FPGA1S.M14@85.05,34.4 ; v1(84.55,37.9) FPGA1S.J14@85.05,37.4 ; FPGA1S.Y14@85.05,26.4 v1(85.55,26.9) ; FPGA1S.P14@85.05,32.4 v1(85.55,32.9) ; FPGA1S.L14@85.05,35.4 v1(85.55,35.9) ; FPGA1S.K14@85.05,36.4 v1(85.55,36.9) ; FPGA1S.C14@85.05,43.4 v1(85.55,42.9) ; C29S.2@85.55,20.15 85.55,19.3 v1(85.85,19.1) ; C24S.2@85.75,50.45 v1(85.75,51.5) ; C39S.2@88.35,50.45 v1(88.35,51.5) ; v1(90.55,36.9) FPGA1S.J20@91.05,37.4 ; FPGA1S.P20@91.05,32.4 v1(91.55,31.9) ; C2S.2@91.35,20.15 91.35,19.1 v1(91.45,19.1) ; FPGA1S.AA21@92.05,25.4 v1(92.55,24.9) ; FPGA1S.B21@92.05,44.4 v1(92.55,44.9) ; FPGA1S.AB22@93.05,24.4 v1(93.55,23.9) ; FPGA1S.A22@93.05,45.4 v1(93.55,45.9) ; C38S.2@98.1,41.1 98.35,41.1 v1(99.15,41.9) ; C1S.2@98.25,44.7 v1(99.25,44.7)
  Top Layer w0.3: R121.1@12.35,58.6 v3(12.35,60.2) ; v3(12.55,101) C26S.2@13.9,101 ; v3(13.95,60.2) 14.45,59.7 R120.1@14.45,58.7 ; U4.15@17.925,99.375 17.925,97.625 v3(17.95,97.6) ; C23.2@25.15,93.4 25.3,93.4 v3(26.75,93.4) ; C13S.2@69.885,16.095 v1(69.885,17.245) ; v3(96.55,54.1) C25S.2@96.55,55.35 C25S.2@96.55,55.4 ; C8S.2@99.15,23.4 C8S.2@99.2,23.4 v1(100.25,23.4) ; C67S.2@149.35,78.25 150.65,78.25 ; v3(150.65,76.9) 150.65,78.25 ; C66S.2@151.95,78.25 150.65,78.25 ; v3(154.55,76.7) C61S.2@154.55,78.25 ; C68S.2@157.15,74.8 v3(157.15,76.7) C64S.2@157.15,78.25 ; C63S.2@159.75,78.25 159.75,77.3 v3(160.15,76.9)
  Top Layer w0.4: v3(1.45,21.8) 2.05,21.2 C4.2@2.05,20 C4.2@2.05,19.9 ; v3(1.55,9.2) 1.6,9.25 R4.2@1.6,10.8 ; C9.1@3.175,31.435 C14.1@5.715,31.435 5.985,31.435 C11.1@7.95,33.4 ; R35S.1@4.55,63.15 4.55,64.6 4.75,64.8 v3(5.35,64.8) 6.15,64.8 7.15,63.8 R36S.1@7.15,63.15 ; C11.1@8.35,33.35 8.35,34.6 8.75,35 v3(9.35,35) ; v3(8.95,43) C39.1@8.95,44.45 ; C15.1@15.95,33.35 15.95,34.4 16.35,34.8 v3(17.15,34.8) 18.15,34.8 18.55,34.4 C17.1@18.55,33.35 ; U2.4@16.455,20 16.455,22.105 v3(16.55,22.2) ; C3S.2@17.95,67.15 18.9,67.15 v3(19.15,66.9) ; C34.1@19.1,51.2 v3(20.75,51.2) ; R5.2@23.35,23.95 v3(23.35,25.6) ; v3(25.15,34.6) C16.1@26.35,33.35 C16.1@26.35,33.2 ; C26.1@49.35,33.7 49.53,33.7 50.75,33.7 v1(50.95,33.9) 50.96,33.89 U5.12@52.21,33.89 53.26,33.89 v1(53.45,33.7) ; S1.16@49.53,11.62 R74.1@49.53,14.29 ; S1.15@52.07,11.62 R75.1@52.07,14.29 ; SW1.3@53.04,53.775 v3(53.04,57.8) SW1.4@53.04,61.785 ; S1.14@54.61,11.62 R76.1@54.61,14.29 ; S1.13@57.15,11.62 R77.1@57.15,14.2 ; S1.12@59.69,11.62 R78.1@59.69,14.29 ; v1(62.05,34.7) 62.06,34.69 U5.34@63.36,34.69 65.25,34.69 65.35,34.69 v1(66.35,34.7) 67.647,34.691 67.648,34.691 C28.1@67.75,34.69 ; S1.11@62.23,11.62 R79.1@62.23,14.29 ; S1.10@64.77,11.62 R80.1@64.77,14.29 ; SW2.3@65.74,53.775 v3(65.74,57.8) SW2.4@65.74,61.785 ; S1.9@67.31,11.62 R81.1@67.31,14.29 ; v1(77.05,19) C36S.2@77.05,20.15 ; SW3.3@78.44,53.775 v1(78.44,57.8) SW3.4@78.44,61.785 ; SW4.3@91.14,53.775 v3(91.14,57.8) SW4.4@91.14,61.785 ; C4S.2@93.45,50.45 v1(93.45,51.5) ; R83.1@95.25,108.265 97.885,108.265 98.55,107.6 98.55,105.435 J2S.3@98.55,105.2 ; C27.1@98.65,35.8 v1(99.65,36.8) ; U6.12@101.575,33.8 v1(102.85,33.8) ; SW5.3@103.84,53.775 v3(103.84,57.8) SW5.4@103.84,61.785 ; v1(111.15,34.8) 111.35,34.6 U6.34@112.725,34.6 113.65,34.6 113.85,34.8 114.935,34.8 C25.1@115.05,34.8 ; v3(114.95,22.6) 115.65,22.6 116.52,21.73 C30.1@116.52,20.955 ; C25.1@114.95,35.2 114.95,35.24 v1(114.95,36.6) ; C56S.2@115.35,15.6 115.45,15.6 v3(117.15,15.6) 117.95,15.6 118.11,15.76 U3.7@118.11,17.915 ; SW6.3@116.54,53.775 v3(116.54,57.8) SW6.4@116.54,61.785 ; C30.1@116.55,20.8 116.55,20.925 C30.1@116.52,20.955 ; C32.1@119.065,20.955 C30.1@116.52,20.955 ; U3.11@121.92,12.565 121.92,14.17 122.35,14.6 124.55,14.6 ; U3.13@124.46,12.565 124.46,14.09 124.55,14.6 ; v3(126.85,17.6) 126.9,17.65 C31.2@128.35,17.65 ; C29.1@127.95,14.6 v3(126.75,14.6) 124.55,14.6 ; v3(134.95,96.4) C65S.2@134.95,98.05 ; SW7.3@145.08,5.96 v3(149.09,5.96) SW7.4@152.95,5.96 SW7.4@153.09,5.96 ; R8S.1@147.75,63.4 147.75,63.1 R7S.1@149.55,61.3 ; v3(149.45,73.3) 149.7,73.05 R5S.1@149.7,71.8 ; R7S.1@149.7,60.8 149.7,59.25 v3(149.75,59.2) ; v1(151.85,55.6) 153.67,55.6 C75S.2@153.75,55.6 ; v3(152.95,65.4) 152.95,66.275 U1S.10@152.95,66.3 ; C75S.2@153.67,55.475 154.325,55.475 154.45,55.6 v1(155.65,55.6) ; C21S.2@156.15,62.3 C21S.2@156.15,61.95 156.15,61.1 v3(156.65,60.6) R6S.1@158.6,60.6 ; C68S.2@156.85,74 C68S.2@157,73.85 ; C68S.2@157,74.6 C68S.2@157,73.85 ; v3(157.75,73.1) C68S.2@157,73.85 ; C79S.1@159.55,20.9 159.55,23.4 160,23.85 C72S.2@160,25.676 ; v1(160.65,101.3) 160.95,101 C62S.2@160.95,99.95
  Top Layer w0.5: C59S.2@100.15,50.5 v3(100.15,52.2) ; C59S.2@101.35,51 v3(101.35,52.2) ; R31S.1@155.89,20.32 157.33,20.32 v3(157.35,20.3) ; D2S.1@162.875,12.53 162.875,11.575 v3(163.35,11.1)
  Top Layer w0.6: v3(1.35,26.2) 2.6,24.95 R8.2@2.75,24.95 ; v3(9.55,19.6) C3.2@9.55,21.7 ; v3(10.55,55.2) C5.2@12.65,55.2 ; v3(11.95,52.6) U1.4@14.35,52.6 ; U1.4@14.35,52.505 16.055,52.505 v3(16.35,52.8) ; v3(46.65,41.3) 48.45,41.3 v3(50.35,41.3) ; C54S.2@63.15,49.7 v3(63.15,51.6) ; C58S.2@67.15,49.7 v3(67.15,51.6) ; C57S.2@81.95,12.9 v1(81.95,14.2) ; C57S.2@83.15,13.1 v1(83.15,14.2) ; C60S.2@97.15,27.9 98.85,27.9 v1(98.85,28.1)
  Top Layer w0.9: v3(9.35,96) C18.2@9.35,97.8 ; v3(153.65,37) 153.67,36.98 C77S.2@153.67,35.155 ; C78S.2@153.67,25.805 155.455,25.805 v3(155.55,25.9) ; C76S.2@153.67,46.76 155.61,46.76 v3(155.65,46.8) ; R34S.1@155.89,41.275 155.89,40.06 156.15,39.8 157.75,39.8 157.955,40.005 GJ2S.1@159.385,40.005
  Top Layer w1: v3(14.15,64.6) 15.05,63.6 15.016,62.766 15.081,62.858 15.25,63.1 C74S.2@15.45,62.6 ; C73S.2@18.95,62 v3(21.15,62) ; v3(48.75,24.2) C19.2@48.75,25.9 C19.2@48.75,26 ; D1S.1@114.15,111.2 114.288,110.8 114.373,110.8 v4(116.55,110.8) ; D1S.1@114.288,111.76 114.283,111.781 114.15,112.4 114.288,112.8 114.373,112.8 v4(116.55,112.8)
  Bottom Layer w0.127: C5S.2@76.55,29.15 76.7,29.15 76.95,28.9 v1(77.55,28.9)
  Bottom Layer w0.2: C27S.2@72.15,36.15 73.1,36.15 73.85,36.9 v1(74.55,36.9) ; C15S.2@72.25,31.9 v1(73.55,31.9) ; v1(73.55,40.9) 74.45,40.9 74.55,41 C34S.2@74.55,41.15 ; C34S.2@74.55,40.9 v1(75.55,40.9) C45S.2@76.35,40.9 ; C45S.2@76.55,40.9 76.575,40.875 v1(77.55,39.9) ; C11S.2@78.55,32.85 79.5,32.85 v1(79.55,32.9) ; C49S.2@78.55,36.9 v1(79.55,36.9) ; C50S.2@78.65,26.9 v1(79.55,26.9) ; C32S.2@78.65,42.9 v1(79.55,42.9) ; C47S.2@80.55,30.85 80.55,30.9 81.25,31.6 81.25,32.2 v1(80.55,32.9) ; C12S.2@80.55,40.85 80.7,40.85 80.75,40.9 v1(81.55,40.9) ; v1(81.55,27.9) 82.3,27.15 C80S.2@82.55,27.15 ; v1(81.55,32.9) C30S.2@82.55,32.9 ; v1(81.55,36.9) C23S.2@82.55,36.9 ; C30S.2@82.55,32.85 C30S.2@82.55,32.9 ; v1(82.55,33.9) C30S.2@82.55,32.9 ; v1(82.55,35.9) C23S.2@82.55,36.9 ; C28S.2@82.55,42.85 v1(83.55,41.9) ; v1(83.55,32.9) C30S.2@82.55,32.9 ; v1(83.55,36.9) C23S.2@82.55,36.9 ; C43S.2@84.55,30.85 84.55,30.9 83.85,31.6 83.85,32.2 v1(84.55,32.9) ; v1(84.55,37.9) C44S.2@84.55,39.15 ; v1(85.55,26.9) C46S.2@86.55,26.9 ; v1(85.55,32.9) 86.5,32.8 C42S.2@86.55,32.85 ; v1(85.55,36.9) C41S.2@86.55,36.9 ; v1(85.55,42.9) 86.25,42.9 86.3,42.85 C19S.2@86.55,42.85 ; C37S.2@87.25,20.15 87.3,20.1 v1(88.25,20.1) ; v1(87.55,29.9) 88.25,29.2 C48S.2@88.55,29.2 ; v1(87.55,40.9) 88.25,40.9 88.35,40.8 C31S.2@88.55,40.8 ; v1(90.55,36.9) C33S.2@91.65,36.9 ; v1(91.55,31.9) C14S.2@92.65,31.9
  Bottom Layer w0.3: v1(93.55,23.9) 93.75,24.1 C9S.2@93.75,25.95
  Bottom Layer w0.4: v1(53.45,33.7) 54.61,33.7 C18S.2@54.75,33.7 ; C17S.2@61.05,34.7 v1(62.05,34.7) ; v1(102.85,33.8) 103.15,33.5 C20S.2@103.95,33.5 ; C6S.2@109.95,34.8 v1(111.15,34.8)
GREEN0: FPGA1S.D10 R103.1 | length 59.8
  Top Layer w0.2: R103.1@61.35,94.05 61.35,92.9 62.25,92 62.25,89.8 64.05,88 v1(64.05,84.3) ; v1(76.55,53.6) 78.85,51.3 78.85,48 80.55,46.3 80.55,42.9 FPGA1S.D10@81.05,42.4
  MidLayer1 w0.2: v1(64.05,84.3) 64.05,78.9 64.95,78 64.95,75.1 75.65,64.4 75.65,55.7 76.55,54.8 v1(76.55,53.6)
GREEN1: FPGA1S.C11 R105.1 | length 60.9
  Top Layer w0.2: R105.1@63.95,94.05 63.95,93.1 64.75,92.3 64.75,90 68.05,86.7 v1(68.05,83.2) ; v1(81.55,42.9) FPGA1S.C11@82.05,43.4
  MidLayer1 w0.2: v1(68.05,83.2) 68.047,82.398 67.501,81.849 67.501,74.749 76.45,65.8 76.45,56.1 77.55,55 77.55,51.6 80.75,48.4 80.75,47.4 82.55,45.6 82.55,43.1 82.35,42.9 v1(81.55,42.9)
GREEN2: FPGA1S.E11 R110.1 | length 61.4
  Top Layer w0.2: R110.1@66.55,94.05 66.55,93.5 67.25,92.8 67.25,90 70.75,86.5 v1(70.75,83.7) ; v1(81.55,41.9) FPGA1S.E11@82.05,41.4
  MidLayer1 w0.2: v1(70.75,83.7) 70.05,83 70.05,74.6 77.25,67.4 77.25,57 78.35,55.9 78.35,53.1 82.95,48.5 82.95,42.3 82.55,41.9 v1(81.55,41.9)
GREEN#: J5.2 R104.2 R105.2 R110.2 | length 16
  Top Layer w0.4: R104.2@58.75,95.95 58.75,97.2 59.15,97.6 63.95,97.6 ; R105.2@63.95,95.95 63.95,97.6 ; J5.2@64.774,100.965 64.774,99.024 63.95,98.2 63.95,97.6 ; R110.2@66.55,95.95 66.55,97.2 66.15,97.6 63.95,97.6
HARD_TCK: R11S.1 U1S.7 | length 3.9
  Top Layer w0.4: R11S.1@149.7,66.6 149.7,66.65 151.275,68.225 U1S.7@152.875,68.225
HARD_TDI: R9S.1 U1S.5 | length 3.3
  Top Layer w0.4: R9S.1@149.7,69.2 150.85,69.2 151.175,69.525 U1S.5@152.875,69.525
HARD_TDO: R10S.1 U1S.17 | length 20.8
  Top Layer w0.4: R10S.1@158.6,58 154.55,58 153.45,59.1 153.45,61 155.25,62.8 155.25,68.8 156.625,70.175 U1S.17@159.425,70.175
HARD_TMS: R12S.1 U1S.9 | length 5.9
  Top Layer w0.4: U1S.9@152.875,66.925 154.325,66.925 154.55,66.7 154.55,63.7 154.25,63.4 R12S.1@153.5,63.4
HSYNC: FPGA1S.A8 R94.1 | length 70.1
  Top Layer w0.2: R94.1@48.35,99.05 53.2,99.05 v1(53.25,99.1) ; v1(77.85,48.7) 77.85,47.7 78.35,47.2 78.35,46.1 FPGA1S.A8@79.05,45.4
  Top Layer w0.4: R94.1@48.2,99.05 R94.1@48.35,99.05
  MidLayer1 w0.2: v1@53.25,99 v1(53.25,99.1) 57.15,95.2 57.15,85.4 58.25,84.3 58.25,82.3 59.875,80.675 59.875,74.675 74.05,60.5 74.05,53.9 75.05,52.9 75.05,50.8 75.75,50.1 76.65,50.1 77.85,48.9 v1(77.85,48.7)
IO0: FPGA1S.V7 HDR1.2 | length 24.1
  Top Layer w0.2: FPGA1S.V7@78.05,28.4 77.55,27.9 77.55,23.9 77.85,23.6 77.85,10.5 81.915,6.435 HDR1.2@81.915,6.35
IO1: FPGA1S.AA8 HDR1.3 | length 25.3
  Top Layer w0.2: FPGA1S.AA8@79.05,25.4 78.55,24.9 78.55,24.166 78.25,23.866 78.25,10.7 80.15,8.8 81.45,8.8 83.15,7.1 83.15,5.115 HDR1.3@84.455,3.81
IO2: FPGA1S.AB8 HDR1.4 | length 22
  Top Layer w0.2: FPGA1S.AB8@79.05,24.4 79.05,24.1 78.65,23.7 78.65,10.9 80.35,9.2 82.655,9.2 84.455,7.4 HDR1.4@84.455,6.35
IO3: FPGA1S.V8 HDR1.5 | length 29.5
  Top Layer w0.2: FPGA1S.V8@79.05,28.4 v1(79.55,27.9)
  MidLayer1 w0.2: v1(79.55,27.9) 78.95,27.3 78.95,26.5 79.25,26.2 79.25,11.2 83.15,7.3 83.15,5.7 83.75,5.1 85.705,5.1 HDR1.5@86.995,3.81
IO4: FPGA1S.Y10 HDR1.6 | length 26.5
  Top Layer w0.2: FPGA1S.Y10@81.05,26.4 80.55,25.9 79.75,25.9 79.55,25.7 79.55,24 79.05,23.5 79.05,11.2 80.65,9.6 83.35,9.6 85.523,7.427 85.918,7.427 HDR1.6@86.995,6.35
IO5: FPGA1S.V9 HDR1.7 | length 30.4
  Top Layer w0.2: FPGA1S.V9@80.05,28.4 v1(80.55,27.9)
  MidLayer1 w0.127: 80.05,26.4 80.05,27.4
  MidLayer1 w0.2: 79.75,25.7 79.75,25.8 ; 80.05,26.4 79.75,26.1 79.75,25.8 ; 80.05,27.4 v1(80.55,27.9) ; HDR1.7@89.535,3.81 88.245,5.1 86.35,5.1 85.75,5.7 85.75,7.1 79.75,13.1 79.75,25.8
IO6: FPGA1S.W9 HDR1.8 | length 26.4
  Top Layer w0.2: FPGA1S.W9@80.05,27.4 v1(80.55,26.9)
  MidLayer1 w0.2: v1(80.55,26.9) 80.55,25.3 81.25,24.6 81.25,12.2 84.446,9.004 85.75,7.7 88.185,7.7 HDR1.8@89.535,6.35
IO7: FPGA1S.AA10 HDR1.9 | length 31.1
  Top Layer w0.2: FPGA1S.AA10@81.05,25.4 80.55,24.9 80.55,24.1 79.45,23 79.45,11.6 80.85,10.2 81.05,10 83.55,10 85.695,7.855 87.395,7.855 88.25,7 88.25,5.8 89.05,5 90.85,5 HDR1.9@92.04,3.81 ; HDR1.9@92.04,3.81 HDR1.9@92.075,3.81 HDR1.9@92.04,3.81
IO8: FPGA1S.AB10 HDR1.10 | length 27.7
  Top Layer w0.2: FPGA1S.AB10@81.05,24.4 81.05,23.7 81.35,23.4 81.35,18.7 79.95,17.3 79.95,11.8 81.35,10.4 83.75,10.4 85.85,8.3 89.15,8.3 89.85,7.6 90.825,7.6 HDR1.10@92.075,6.35
IO9: FPGA1S.W10 HDR1.11 | length 35.1
  Top Layer w0.2: FPGA1S.W10@81.05,27.4 81.55,26.9 81.55,23.8 81.75,23.6 81.75,18.4 80.45,17.1 80.45,12 81.65,10.8 83.95,10.8 86.05,8.7 89.35,8.7 90.05,8 92.75,8 93.35,7.4 93.35,5.075 HDR1.11@94.615,3.81
IO10: FPGA1S.AB11 HDR1.12 | length 27.4
  Top Layer w0.2: FPGA1S.AB11@82.05,24.4 82.05,23.9 82.25,23.7 82.25,19.2 84.05,17.4 84.05,11.3 86.25,9.1 89.55,9.1 90.25,8.4 93.95,8.4 94.615,7.735 HDR1.12@94.615,6.35
IO11: FPGA1S.U11 HDR1.13 | length 36.2
  Top Layer w0.2: FPGA1S.U11@82.05,29.4 82.55,28.9 82.55,24.1 82.65,24 82.65,19.4 84.45,17.6 84.45,11.5 86.45,9.5 89.75,9.5 90.45,8.8 94.55,8.8 95.85,7.5 95.85,5.115 HDR1.13@97.155,3.81
IO12: FPGA1S.AB13 HDR1.14 | length 27.6
  Top Layer w0.2: FPGA1S.AB13@84.05,24.4 84.05,19.2 85.65,17.6 85.65,12.1 87.85,9.9 89.95,9.9 90.65,9.2 95.65,9.2 97.155,7.695 HDR1.14@97.155,6.35
IO13: FPGA1S.AA13 HDR1.15 | length 32.8
  Top Layer w0.2: FPGA1S.AA13@84.05,25.4 84.55,24.9 84.55,19.4 86.05,17.9 86.05,12.3 88.05,10.3 90.25,10.3 90.95,9.6 96.75,9.6 98.45,7.9 98.45,5.055 HDR1.15@99.695,3.81
IO14: FPGA1S.V10 HDR1.16 | length 37.8
  Top Layer w0.2: FPGA1S.V10@81.05,28.4 v1(81.55,28.9)
  MidLayer1 w0.2: v1(81.55,28.9) 82.15,28.3 82.15,18.2 82.55,17.8 82.55,11.5 85.95,8.1 97.95,8.1 99.695,6.355 HDR1.16@99.695,6.35
IO15: FPGA1S.U10 HDR1.17 | length 43.4
  Top Layer w0.2: FPGA1S.U10@81.05,29.4 v1(81.55,29.9)
  MidLayer1 w0.2: v1(81.55,29.9) 82.55,28.9 82.55,18.6 83.75,17.4 83.75,10.9 86.05,8.6 99.85,8.6 100.95,7.5 100.95,5.095 HDR1.17@102.235,3.81
IO16: FPGA1S.W13 HDR1.18 | length 38.3
  Top Layer w0.2: v1(83.55,26.9) FPGA1S.W13@84.05,27.4
  MidLayer1 w0.2: v1(83.55,26.9) 82.95,26.3 82.95,18.8 84.15,17.6 84.15,11.1 86.25,9 101.35,9 102.235,8.115 HDR1.18@102.235,6.35
IO17: FPGA1S.Y13 HDR1.19 | length 41
  Top Layer w0.2: v1(83.55,25.9) FPGA1S.Y13@84.05,26.4
  MidLayer1 w0.2: v1(83.55,25.9) 83.55,18.8 84.65,17.7 84.65,12.3 84.55,12.2 84.55,11.3 86.35,9.5 102.25,9.5 103.45,8.3 103.45,5.135 HDR1.19@104.775,3.81
IO18: FPGA1S.V14 HDR2.2 | length 50.8
  Top Layer w0.2: v1(84.55,27.9) FPGA1S.V14@85.05,28.4
  MidLayer1 w0.2: v1(84.55,27.9) 84.55,19 85.45,18.1 85.45,12.9 88.05,10.3 107.35,10.3 110.15,7.5 116.29,7.5 HDR2.2@117.44,6.35
IO19: FPGA1S.V13 HDR2.3 | length 55.1
  Top Layer w0.2: v1(83.55,27.9) FPGA1S.V13@84.05,28.4
  MidLayer1 w0.2: v1(83.55,27.9) 84.15,27.3 84.15,18.8 85.05,17.9 85.05,12.7 87.85,9.9 104.25,9.9 109.05,5.1 118.69,5.1 HDR2.3@119.98,3.81
IO20: FPGA1S.AA15 HDR2.4 | length 50.6
  Top Layer w0.2: FPGA1S.AA15@86.05,25.4 85.55,24.9 85.55,23.8 86.45,22.9 86.45,12.5 88.25,10.7 90.65,10.7 91.35,10 104.15,10 109.05,5.1 118.73,5.1 HDR2.4@119.98,6.35
IO21: FPGA1S.W14 HDR2.5 | length 57.9
  Top Layer w0.2: FPGA1S.W14@85.05,27.4 v1(85.55,27.9)
  MidLayer1 w0.2: v1(85.55,27.9) 84.95,27.3 84.95,19.2 85.85,18.3 85.85,13.1 88.25,10.7 107.55,10.7 110.35,7.9 120.55,7.9 121.25,7.2 121.25,5.08 HDR2.5@122.52,3.81
IO22: FPGA1S.AB15 HDR2.6 | length 50.3
  Top Layer w0.2: FPGA1S.AB15@86.05,24.4 86.05,23.9 86.85,23.1 86.85,12.7 87.076,12.474 88.45,11.1 90.85,11.1 91.55,10.4 106.35,10.4 109.25,7.5 121.37,7.5 HDR2.6@122.52,6.35
IO23: FPGA1S.Y16 HDR2.7 | length 57
  Top Layer w0.2: FPGA1S.Y16@87.05,26.4 86.55,25.9 86.55,24 87.25,23.3 87.25,12.9 88.65,11.5 91.05,11.5 91.75,10.8 106.55,10.8 109.45,7.9 123.35,7.9 123.75,7.5 123.75,5.12 HDR2.7@125.06,3.81
IO24: FPGA1S.AA17 HDR2.8 | length 52.6
  Top Layer w0.2: FPGA1S.AA17@88.05,25.4 87.55,24.9 87.55,23.7 87.65,23.6 87.65,14.8 88.05,14.4 92.25,14.4 95.45,11.2 106.75,11.2 109.65,8.3 124.55,8.3 125.06,7.79 HDR2.8@125.06,6.35
IO25: FPGA1S.AA18 HDR2.9 | length 53.6
  Top Layer w0.2: FPGA1S.AA18@89.05,25.4 88.55,24.9 88.55,23.7 88.85,23.4 88.85,18.4 95.65,11.6 106.95,11.6 109.85,8.7 125.25,8.7 126.35,7.6 126.35,5.06 HDR2.9@127.6,3.81
IO26: FPGA1S.AB18 HDR2.10 | length 50.1
  Top Layer w0.2: FPGA1S.AB18@89.05,24.4 89.05,23.8 89.25,23.6 89.25,18.6 95.85,12 107.15,12 110.05,9.1 126.15,9.1 127.6,7.65 HDR2.10@127.6,6.35
IO27: FPGA1S.Y18 HDR2.11 | length 56.5
  Top Layer w0.2: FPGA1S.Y18@89.05,26.4 89.55,25.9 89.55,24 89.65,23.9 89.65,18.8 96.05,12.4 107.35,12.4 110.25,9.5 127.75,9.5 128.85,8.4 128.85,5.1 HDR2.11@130.14,3.81
IO28: FPGA1S.Y19 HDR2.12 | length 54.6
  Top Layer w0.2: FPGA1S.Y19@90.05,26.4 90.55,25.9 90.55,24 90.05,23.5 90.05,19 96.25,12.8 107.55,12.8 110.45,9.9 129.05,9.9 130.14,8.81 HDR2.12@130.14,6.35
IO29: FPGA1S.AB20 HDR2.13 | length 56.3
  Top Layer w0.2: FPGA1S.AB20@91.05,24.4 91.05,23.5 90.45,22.9 90.45,19.2 96.45,13.2 107.75,13.2 110.65,10.3 130.05,10.3 131.45,8.9 131.45,5.04 HDR2.13@132.68,3.81
IO30: FPGA1S.AA20 HDR2.14 | length 54.3
  Top Layer w0.2: FPGA1S.AA20@91.05,25.4 91.55,24.9 91.55,23.8 92.15,23.2 92.15,18.1 96.65,13.6 107.95,13.6 110.85,10.7 130.35,10.7 132.68,8.37 HDR2.14@132.68,6.35
IO31: FPGA1S.U16 HDR2.15 | length 71.4
  Top Layer w0.2: v1(86.55,29.9) FPGA1S.U16@87.05,29.4
  MidLayer1 w0.2: v1(86.55,29.9) 86.15,29.5 86.15,19.6 86.45,19.3 86.45,13.1 88.45,11.1 107.75,11.1 110.55,8.3 122.85,8.3 123.75,7.4 123.75,5.7 124.35,5.1 133.93,5.1 HDR2.15@135.22,3.81
IO32: FPGA1S.V16 HDR2.16 | length 68.1
  Top Layer w0.2: FPGA1S.V16@87.05,28.4 v1(87.55,28.9)
  MidLayer1 w0.2: v1(87.55,28.9) 86.55,27.9 86.55,19.9 86.85,19.6 86.85,13.3 88.65,11.5 107.95,11.5 110.75,8.7 123.95,8.7 124.95,7.7 133.87,7.7 HDR2.16@135.22,6.35
IO33: FPGA1S.V17 HDR2.17 | length 70.8
  Top Layer w0.2: v1(87.55,27.9) FPGA1S.V17@88.05,28.4
  MidLayer1 w0.2: v1(87.55,27.9) 86.95,27.3 86.95,20.1 87.25,19.8 87.25,14.3 87.55,14 89.75,14 91.85,11.9 108.15,11.9 110.95,9.1 124.15,9.1 125.15,8.1 135.55,8.1 136.45,7.2 136.45,5.12 HDR2.17@137.76,3.81
IO34: FPGA1S.W16 HDR2.18 | length 67.3
  Top Layer w0.2: FPGA1S.W16@87.05,27.4 v1(87.55,26.9)
  MidLayer1 w0.2: v1(87.55,26.9) 87.35,26.7 87.35,20.4 87.65,20.1 87.65,14.9 88.15,14.4 89.95,14.4 92.05,12.3 108.35,12.3 111.15,9.5 124.35,9.5 125.25,8.6 136.75,8.6 137.76,7.59 HDR2.18@137.76,6.35
IO35: FPGA1S.W17 HDR2.19 | length 70.6
  Top Layer w0.2: FPGA1S.W17@88.05,27.4 v1(88.55,26.9)
  MidLayer1 w0.2: v1(88.55,26.9) 87.75,26.1 87.75,24.5 88.85,23.4 88.85,18.8 90.35,17.3 90.35,14.6 92.25,12.7 108.55,12.7 111.35,9.9 124.55,9.9 125.45,9 138.15,9 138.95,8.2 138.95,5.16 HDR2.19@140.3,3.81
KBCLOCK: FPGA1S.F20 R89.1 | length 84.7
  Top Layer w0.2: FPGA1S.F20@91.05,40.4 v1(91.55,39.9) ; R89.1@119.35,98.05 119.35,96.6 121.55,94.4 121.55,80.7 120.75,79.9 120.75,64.3 v1(122.25,62.8)
  MidLayer1 w0.2: v1(91.55,39.9) 92.45,39.9 93.35,39 99.65,39 102.15,41.5 111.05,41.5 118.65,49.1 118.65,56.1 122.25,59.7 v1(122.25,62.8)
KBDATA: FPGA1S.G19 R88.1 | length 85.9
  Top Layer w0.2: FPGA1S.G19@90.05,39.4 v1(90.55,39.9) ; R88.1@121.95,98.05 121.95,80.3 121.15,79.5 121.15,65.4 v1(122.95,63.6)
  MidLayer1 w0.2: v1(90.55,39.9) 91.25,39.2 92.25,39.2 92.85,38.6 99.85,38.6 102.25,41 111.15,41 119.05,48.9 119.05,55.9 122.95,59.8 v1(122.95,63.6)
LED0: FPGA1S.W2 LD0.1 | length 27.8
  Top Layer w0.2: LD0.1@49.53,20.635 49.53,23.08 50.95,24.5 68.95,24.5 71.35,26.9 72.55,26.9 FPGA1S.W2@73.05,27.4
LED1: FPGA1S.Y1 LD1.1 | length 23.9
  Top Layer w0.2: LD1.1@52.07,20.635 52.07,23.22 52.95,24.1 69.15,24.1 71.45,26.4 FPGA1S.Y1@72.05,26.4
LED2: FPGA1S.Y2 LD2.1 | length 22.3
  Top Layer w0.2: LD2.1@54.61,20.635 54.61,23.16 55.15,23.7 69.35,23.7 71.55,25.9 72.55,25.9 FPGA1S.Y2@73.05,26.4
LED3: FPGA1S.Y3 LD3.1 | length 21.1
  Top Layer w0.2: LD3.1@57.15,20.635 57.15,22.6 57.85,23.3 68.15,23.3 68.35,23.1 v1(69.65,23.1) ; v1(73.55,25.9) FPGA1S.Y3@74.05,26.4
  MidLayer1 w0.2: v1(69.65,23.1) 69.65,23.9 71.65,25.9 v1(73.55,25.9)
LED4: FPGA1S.W4 LD4.1 | length 20.5
  Top Layer w0.2: LD4.1@59.69,20.635 59.69,22.24 60.35,22.9 67.95,22.9 68.35,22.5 v1(68.95,22.5) ; v1(74.55,26.9) FPGA1S.W4@75.05,27.4
  MidLayer1 w0.2: v1(68.95,22.5) 72.05,22.5 74.55,25 v1(74.55,26.9)
LED5: FPGA1S.W5 LD5.1 | length 19
  Top Layer w0.2: LD5.1@62.23,20.635 62.23,20.8 62.25,20.82 v1(62.25,22.3) ; v1(75.55,26.9) FPGA1S.W5@76.05,27.4
  MidLayer1 w0.2: v1(62.25,22.3) 63.25,22.3 63.55,22.6 67.15,22.6 67.85,21.9 72.05,21.9 74.95,24.8 74.95,26.3 v1(75.55,26.9)
LED6: FPGA1S.Y5 LD6.1 | length 15.2
  Top Layer w0.2: LD6.1@64.75,21 v1(64.75,21.9) ; v1(75.55,25.9) FPGA1S.Y5@76.05,26.4
  MidLayer1 w0.2: v1(64.75,21.9) 65.35,21.3 72.05,21.3 75.55,24.8 v1(75.55,25.9)
LED7: FPGA1S.W6 LD7.1 | length 13.9
  Top Layer w0.2: LD7.1@67.31,20.895 68.255,20.895 68.55,20.6 v1(71.85,20.6) ; v1(76.55,26.9) FPGA1S.W6@77.05,27.4
  MidLayer1 w0.127: 76.05,25.4 76.05,26.4
  MidLayer1 w0.2: v1(71.85,20.6) 72.35,20.6 76.05,24.3 76.05,25.4 ; 76.05,26.4 v1(76.55,26.9)
LED_DONE: FPGA1S.AB21 R24.1 | length 51.5
  Top Layer w0.2: FPGA1S.AB21@92.05,24.4 92.05,23.9 92.55,23.4 92.55,18.3 96.85,14 108.15,14 111.05,11.1 133.25,11.1 133.55,11.4 R24.1@133.55,12.45
MOUSECLOCK: FPGA1S.L17 R93.1 | length 124.3
  Top Layer w0.2: FPGA1S.L17@88.05,35.4 v1(88.55,35.9)
  Top Layer w0.4: R93.1@158.35,99.95 158.35,100.6 v3(159.05,101.3)
  MidLayer1 w0.2: v1(88.55,35.9) 88.55,36.9 89.45,37.8 ; 89.25,37.6 89.45,37.8 ; v1(124.15,65) 124.15,59.8 119.85,55.5 119.85,48.5 111.35,40 102.45,40 100.25,37.8 89.45,37.8
  Bottom Layer w0.4: 123.05,80.5 123.05,79.7 121.65,78.3 121.65,67.5 v1(124.15,65) ; 123.05,80.6 123.05,81.5 127.75,86.2 127.75,93.2 129.45,94.9 137.05,94.9 138.95,96.8 154.55,96.8 v3(159.05,101.3)
MOUSEDATA: FPGA1S.G18 R92.1 | length 72.8
  Top Layer w0.2: FPGA1S.G18@89.05,39.4 v1(89.55,38.9)
  Top Layer w0.3: v1(123.55,64.3) 121.65,66.2 121.65,79.2 123.825,81.375 R92.1@123.825,82.87
  MidLayer1 w0.2: v1(89.55,38.9) 90.25,38.2 100.05,38.2 102.35,40.5 111.25,40.5 119.45,48.7 119.45,55.7 123.55,59.8 v1(123.55,64.3)
NetC1_1: C1.1 C8.2 RN1.7 U2.1 | length 35.6
  Top Layer w0.4: C1.1@2.55,16.6 C1.1@2.55,16.7 2.55,17.8 3.15,18.4 v3(6.95,18.4) v3(11.35,18.4) 12.35,18.4 12.645,18.695 U2.1@12.645,20 ; RN1.7@10.795,36.195 10.795,37.545 11,37.75 C8.2@11,39.4
  Bottom Layer w0.4: v3(6.95,18.4) 6.95,30.6 10.795,34.445 RN1.7@10.795,36.195
NetC1_2: C1.2 R2.1 R4.1 | length 6.7
  Top Layer w0.4: R4.1@3.5,10.8 3.5,11.65 2.55,12.6 C1.2@2.55,13.7 5.5,13.7 R2.1@5.8,13.4
NetC2_1: C2.1 C10.2 RN2.7 U2.7 | length 20
  Top Layer w0.4: C10.2@11.2,32.4 11.2,30.25 10.795,29.845 RN2.7@10.795,28.575 11.97,27.4 13.15,27.4 13.915,26.635 U2.7@13.915,25.2 ; v3(17.95,25.4) C2.1@20.15,25.4
  Bottom Layer w0.4: RN2.7@10.795,28.575 13.97,25.4 v3(17.95,25.4)
NetC2_2: C2.2 R3.1 R5.1 | length 8.1
  Top Layer w0.4: C2.2@20.55,22 20.6,22.05 R5.1@23.35,22.05 25.1,22.05 25.35,21.8 25.35,20 25.15,19.8 R3.1@24.1,19.8
NetC5_1: C5.1 C34.2 U1.3 | length 7.9
  Top Layer w0.4: U1.3@14.35,51.235 17.165,51.235 C34.2@17.2,51.2 17.2,54.35 16.35,55.2 C5.1@15.65,55.2
NetC6_2: C6.2 C40.2 RN1.1 | length 18.9
  Top Layer w0.4: RN1.1@26.035,36.195 34.555,36.195 36.46,34.29 C40.2@38.767,34.29 38.767,32.017 37.97,31.22 C6.2@37.97,29.21
NetC7_2: C7.2 C41.2 RN2.1 | length 18.7
  Top Layer w0.4: RN2.1@26.035,28.575 31.575,28.575 34.75,25.4 C7.2@37.97,25.4 37.97,22.58 38.767,21.783 C41.2@38.767,20.32
NetC8_1: C8.1 RN1.6 U2.2 | length 22.8
  Top Layer w0.4: C8.1@12.9,39.4 12.9,37.85 13.335,37.415 RN1.6@13.335,36.195 ; U2.2@13.95,20.2 v3(13.95,22.2)
  Bottom Layer w0.4: RN1.6@13.335,36.195 13.335,34.585 9.55,30.8 9.55,26.6 v3(13.95,22.2)
NetC9_2: C9.2 C14.2 RN1.4 RN1.5 RN1.10 | length 27.5
  Top Layer w0.4: C9.2@3.175,33.335 4.35,33.335 ; RN1.10@3.175,36.195 4.35,36.2 ; C14.2@5.715,33.335 4.35,33.335 ; RN1.5@15.875,36.195 RN1.4@18.415,36.195 ; 17.15,36.2 17.15,38.6 14.95,40.8 8.35,40.8 4.35,36.8 4.35,36.2 ; 4.35,33.335 4.35,36.2
NetC10_1: C10.1 RN2.6 U2.6 | length 8.1
  Top Layer w0.4: C10.1@13.1,32.4 13.1,30.05 13.335,29.815 RN2.6@13.335,28.575 13.375,28.575 15.185,26.765 U2.6@15.185,25.2
NetC11_2: C11.2 C15.2 RN2.4 RN2.5 RN2.10 | length 22.5
  Top Layer w0.4: RN2.10@3.175,28.575 3.175,28.625 4.55,30 6.9,30 C11.2@8.35,31.45 9,31.45 9.75,32.2 9.75,33.6 10.35,34.2 13.35,34.2 14.35,33.2 14.35,32.65 C15.2@15.55,31.45 ; C15.2@15.95,31.45 15.875,31.375 RN2.5@15.875,28.575 RN2.4@18.415,28.575
NetC12_1: C12.1 C16.2 | length 2.6
  Top Layer w0.4: C12.1@23.75,31.45 C16.2@26.35,31.45
NetC12_2: C12.2 RN1.2 RN1.3 | length 6.4
  Top Layer w0.4: RN1.3@20.955,36.195 22.15,36.195 ; RN1.2@23.495,36.195 22.15,36.195 ; C12.2@23.75,33.35 23.75,34.4 23.35,34.8 22.75,34.8 22.15,35.4 22.15,36.195
NetC13_1: C13.1 C17.2 | length 3.2
  Top Layer w0.4: C17.2@18.55,31.45 19,31.45 C13.1@20.95,33.4
NetC13_2: C13.2 RN2.2 RN2.3 | length 5.5
  Top Layer w0.4: C13.2@21.15,31.45 21.15,30 20.955,29.805 RN2.3@20.955,28.575 RN2.2@23.495,28.575
NetC20_1: C20.1 U4.1 | length 5.3
  Top Layer w0.3: C20.1@14.75,94.95 14.75,95.8 14.95,96 16.75,96 17.275,95.475 U4.1@17.275,93.825
NetC20_2: C20.2 U4.3 | length 6.4
  Top Layer w0.3: C20.2@14.75,93.05 14.75,92.2 15.15,91.8 17.75,91.8 18.575,92.625 U4.3@18.575,93.825
NetC21_2: C21.2 U4.2 | length 5.4
  Top Layer w0.3: C21.2@14.75,96.65 16.9,96.65 17.925,95.625 U4.2@17.925,93.825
